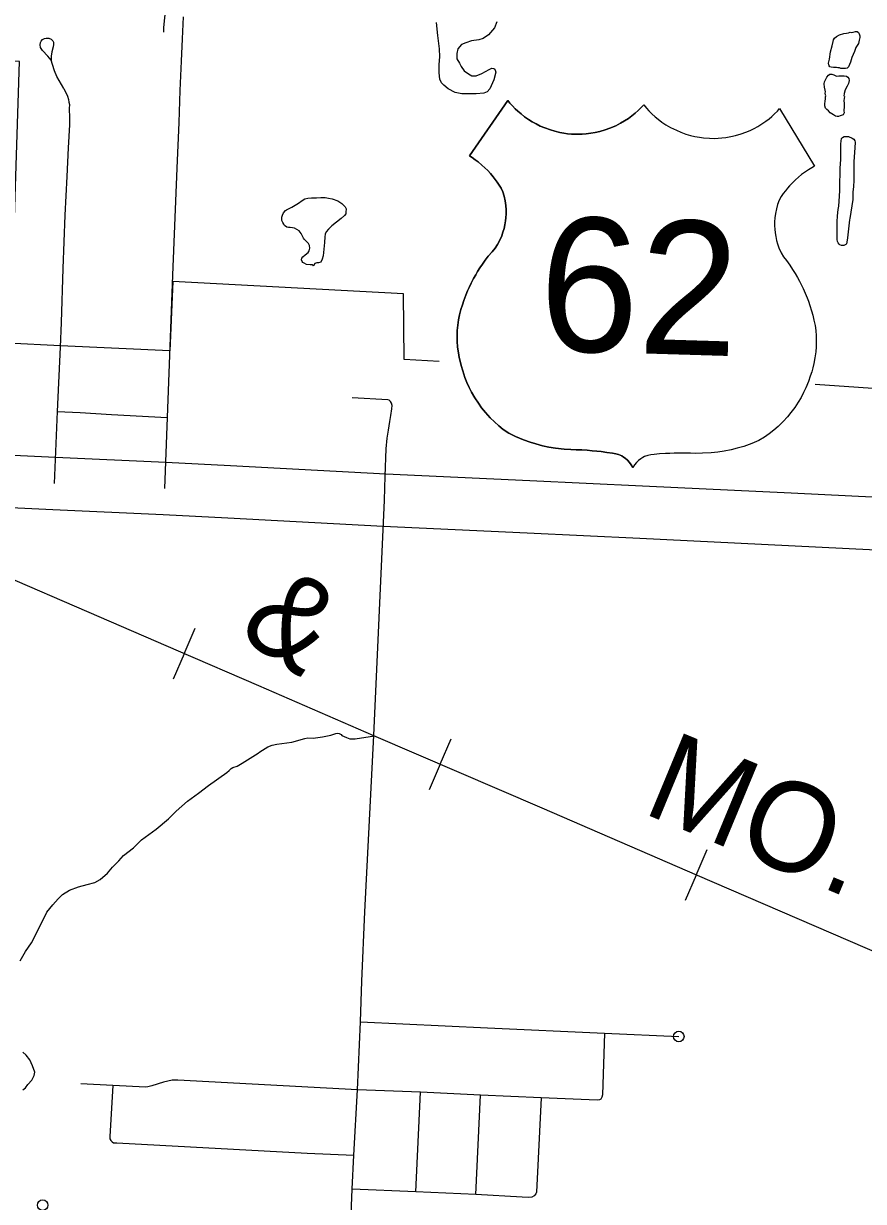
# Model space of a CAD drawing. Extents: x 653372 to 905732, y 627442 to 787275.
# Drawn here: x 676978 to 680953, y 739676 to 745249 of the extents above; entities that cross this region are included whole.
import ezdxf

# ---------------------------------------------------------------- set-up
doc = ezdxf.new("R2010")
doc.units = 0
for name, color, linetype in [('15', 7, 'Continuous'), ('22', 7, 'Continuous'), ('33', 7, 'Continuous'), ('34', 7, 'Continuous'), ('35', 7, 'Continuous'), ('40', 7, 'Continuous'), ('49', 7, 'Continuous'), ('6', 7, 'Continuous')]:
    doc.layers.add(name, color=color, linetype=linetype)

msp = doc.modelspace()

# ---------------------------------------------------------------- linework, layer by layer
at = {"layer": '15'}
for points in [[(674055.1, 743338.2), (674933.5, 743298.8), (675764.1, 743263.3), (676102.5, 743246.2), (677128.2, 743197.8), (677651.3, 743173.3), (677957.3, 743157.7), (678692, 743119.1), (679373.4, 743086.6), (679906.4, 743062.3), (680610.7, 743028), (681281, 742994.8), (682239.3, 742949), (682595.1, 742932.4), (682621, 742930.7), (682881.5, 742919.2), (683054.5, 742911.5), (683924.1, 742873.5), (684678.2, 742833.8)], [(684666.1, 742584.1), (683912, 742623.8), (683043.4, 742661.8), (682870.4, 742669.5), (682607.5, 742681.1), (682581.3, 742682.7), (682227.5, 742699.3), (681268.8, 742745.1), (680598.5, 742778.3), (679894.7, 742812.6), (679361.7, 742836.9), (678679.5, 742869.4), (677944.3, 742908), (677639.1, 742923.6), (677116.5, 742948.1), (676090.3, 742996.5), (675752.4, 743013.6), (674922.5, 743049), (674043.4, 743088.5)]]:
    msp.add_lwpolyline(points, dxfattribs=at)
at = {"layer": '22'}
for points in [[(679913.1, 744864), (679899.5, 744849.6), (679886.5, 744837.1), (679871.8, 744824.1), (679856, 744811.4), (679840.8, 744800.3), (679822.3, 744788.2), (679802.6, 744776.7), (679780.2, 744765.3), (679751.8, 744753.1), (679730.1, 744745.4), (679705.5, 744738.3), (679683.2, 744733.1), (679662.6, 744729.5), (679640.9, 744726.9), (679620.9, 744725.4), (679593.7, 744725), (679571.6, 744725.9), (679552.4, 744727.6), (679534.1, 744730.1), (679515.7, 744733.5), (679492.5, 744738.9), (679471.1, 744745.2), (679445, 744754.6), (679423, 744764), (679403.1, 744773.9), (679384.8, 744784.2), (679368, 744794.7), (679349.2, 744807.9), (679332.1, 744821.3), (679317.3, 744834.1), (679304.9, 744845.8), (679292.3, 744858.8), (679279.9, 744872.6), (679269.9, 744884.7), (679088.9, 744622.4), (679101, 744614.6), (679115.5, 744604.6), (679129.1, 744594.3), (679147.2, 744579.2), (679161.7, 744566), (679174.5, 744553.3), (679187.5, 744539.3), (679200.8, 744523.6), (679210.3, 744511.5), (679219.6, 744498.6), (679229, 744484.6), (679238.2, 744469.8), (679246.5, 744452.6), (679252.6, 744431.5), (679257.1, 744410.7), (679260.2, 744388.5), (679261.7, 744367.9), (679261.8, 744348.1), (679260.7, 744329.6), (679259.1, 744314.7), (679256.1, 744296.6), (679252.2, 744279.5), (679246.8, 744261.1), (679241.1, 744245), (679233.4, 744227), (679221.5, 744203.7), (679209.4, 744185.5), (679195, 744169.3), (679177.4, 744148), (679163.1, 744129.4), (679149.7, 744110.7), (679137.3, 744092.3), (679127, 744075.9), (679117.8, 744060.4), (679107.5, 744042), (679096.4, 744020.5), (679086.3, 743999.5), (679079.4, 743983.8), (679071.1, 743963.7), (679061.9, 743939), (679054.6, 743918.5), (679047.7, 743896), (679041.1, 743869.9), (679036.5, 743846.7), (679033, 743822.4), (679030.6, 743795.8), (679029.7, 743770.8), (679030.1, 743746.3), (679032.2, 743717.5), (679035.9, 743690.2), (679039.7, 743669.5), (679043.9, 743651.3), (679049.2, 743630.7), (679056.4, 743605), (679066.9, 743573.9), (679076.1, 743550.9), (679086.8, 743527.2), (679098.6, 743504), (679114.1, 743477.2), (679130.2, 743452.5), (679145.9, 743431), (679163.8, 743409), (679186.9, 743383.4), (679206.7, 743364), (679227, 743345.9)], [(679913.1, 744864), (679925.8, 744848.8), (679937.9, 744835.6), (679951.8, 744821.7), (679966.9, 744808.1), (679981.4, 744796.1), (679999.1, 744782.9), (680018.1, 744770.2), (680039.8, 744757.5), (680067.4, 744743.6), (680088.6, 744734.6), (680112.7, 744726), (680134.7, 744719.6), (680155, 744714.7), (680176.5, 744710.8), (680196.3, 744708.1), (680223.5, 744706), (680245.6, 744705.6), (680264.9, 744706.2), (680283.3, 744707.6), (680301.9, 744709.9), (680325.4, 744713.9), (680347.1, 744718.9), (680373.7, 744726.7), (680396.2, 744734.8), (680416.7, 744743.5), (680435.6, 744752.6), (680453, 744762.2), (680472.5, 744774.2), (680490.4, 744786.5), (680505.9, 744798.4), (680519, 744809.3), (680532.4, 744821.5), (680545.6, 744834.6), (680556.3, 744846.1), (680721.2, 744573.4), (680708.7, 744566.4), (680693.6, 744557.2), (680679.4, 744547.7), (680660.4, 744533.8), (680645.2, 744521.4), (680631.6, 744509.5), (680617.9, 744496.3), (680603.6, 744481.5), (680593.4, 744469.9), (680583.4, 744457.7), (680573.1, 744444.2), (680563.1, 744430), (680553.7, 744413.3), (680546.4, 744392.7), (680540.7, 744372.1), (680536.2, 744350.1), (680533.5, 744329.7), (680532.2, 744309.9), (680532.1, 744291.4), (680532.9, 744276.5), (680534.8, 744258.2), (680537.7, 744240.9), (680541.9, 744222.2), (680546.7, 744205.8), (680553.2, 744187.3), (680563.8, 744163.4), (680574.8, 744144.5), (680588.2, 744127.4), (680604.4, 744105.2), (680617.6, 744085.7), (680629.9, 744066.2), (680641.1, 744047.2), (680650.5, 744030.1), (680658.7, 744014.2), (680667.9, 743995.1), (680677.7, 743973), (680686.4, 743951.4), (680692.4, 743935.3), (680699.5, 743914.8), (680707.2, 743889.6), (680713.2, 743868.7), (680718.8, 743845.8), (680723.8, 743819.4), (680727, 743795.9), (680729, 743771.4), (680729.8, 743744.8), (680729.2, 743719.8), (680727.3, 743695.4), (680723.5, 743666.7), (680718.2, 743639.7), (680713.1, 743619.2), (680707.9, 743601.3), (680701.4, 743581.1), (680692.7, 743555.9), (680680.3, 743525.4), (680669.8, 743503), (680657.7, 743480.1), (680644.4, 743457.6), (680627.4, 743431.8), (680609.8, 743408.1), (680592.9, 743387.6), (680573.7, 743366.6), (680549, 743342.5), (680528.2, 743324.3), (680506.8, 743307.5)], [(679227, 743345.9), (679248.2, 743328.8), (679273.8, 743311), (679306.1, 743295.4), (679343.9, 743279.5), (679374.9, 743268.4), (679402.8, 743259.8), (679434.4, 743251.5), (679464.1, 743245.1), (679496.1, 743239.7), (679536.4, 743235), (679567.3, 743233), (679593.8, 743232.4), (679619.6, 743231.3), (679645.3, 743229.7), (679669.7, 743227.8), (679691, 743225.7), (679711.9, 743223.3), (679738.7, 743219.7), (679764.9, 743215.7), (679780.6, 743213), (679793.6, 743210), (679809.1, 743203), (679818, 743197.8), (679825.7, 743192.3), (679836.2, 743183.3), (679846.2, 743172.5), (679854.3, 743161.5), (679861.6, 743148.8)], [(680506.8, 743307.5), (680484.6, 743291.7), (680458, 743275.5), (680424.8, 743261.8), (680386.1, 743248.2), (680354.5, 743239), (680326.1, 743232.1), (680294.1, 743225.7), (680264.1, 743221.1), (680231.8, 743217.6), (680191.3, 743215.4), (680160.3, 743215.2), (680133.8, 743216.1), (680108, 743216.6), (680082.3, 743216.6), (680057.8, 743216.1), (680036.4, 743215.3), (680015.4, 743214.2), (679988.4, 743212.2), (679962, 743209.7), (679946.2, 743208), (679933.1, 743205.8), (679917.2, 743199.8), (679908, 743195.1), (679900, 743190.1), (679888.9, 743181.7), (679878.3, 743171.6), (679869.6, 743161), (679861.6, 743148.8)]]:
    msp.add_lwpolyline(points, dxfattribs=at)
at = {"layer": '33'}
for points in [[(677733.3, 745281.3), (677727.7, 745177), (677723.2, 745070.8), (677717.8, 744931.3), (677712.6, 744781.2), (677703, 744564), (677683.3, 744057.5), (677657.9, 743384.7), (677645.2, 743048.5)], [(677168.2, 744941.7), (677185.3, 744904.7), (677190, 744890.2), (677192.5, 744877.3), (677194.7, 744865.1), (677193.5, 744846.2), (677194.4, 744802.7), (677194.4, 744769.7), (677188.9, 744661.4), (677182.6, 744524.9), (677173.2, 744341.7), (677164.4, 744090), (677155.7, 743833.6), (677151, 743717.7), (677136.9, 743413), (677122.3, 743073)], [(678685.8, 742994.2), (678688.7, 743107), (678694.6, 743235.9), (678698.7, 743287.8), (678704.4, 743325.4), (678711.7, 743365.9), (678716.2, 743394.4), (678720.7, 743425.3), (678721.6, 743441.1), (678719.9, 743451.9), (678714, 743460.2), (678708.6, 743466.5), (678702.5, 743467.7), (678533.5, 743477.9)], [(677136.9, 743413), (677245.2, 743408.5), (677393.2, 743399.7), (677657.9, 743384.7)], [(678446, 737776.3), (678468.8, 738303.5), (678483.2, 738601.3), (678499.8, 738933.7), (678512.4, 739223.8), (678533.8, 739734.2), (678541.5, 739894.8), (678558.6, 740203.3), (678572.7, 740525.6), (678579.2, 740718.4), (678593.6, 741046), (678635.3, 741880.7), (678685.8, 742994.2)], [(678572.7, 740525.6), (679173.6, 740497.6), (679727.7, 740471.8), (680078.9, 740456.3)], [(679727.7, 740471.8), (679717.2, 740180.2), (679715.2, 740169.4), (679713.4, 740165.3), (679709.5, 740160), (679703.6, 740156.8), (679693.1, 740155.1), (679428.2, 740166.4), (679141.1, 740179.4), (678856.7, 740192.1), (678558.6, 740203.3)], [(678558.6, 740203.3), (677708, 740250), (677681.5, 740249.2), (677660.6, 740245.6), (677640.3, 740240.4), (677585.1, 740222.1), (677566.7, 740218.5), (677556.4, 740216.3), (677400.5, 740224.3), (677249.5, 740233)], [(677400.5, 740224.3), (677385.8, 739983.6), (677386.3, 739972.7), (677390.2, 739964.3), (677396.7, 739957.4), (677404, 739953.9), (677419.8, 739953.4), (678319.8, 739904), (678541.5, 739894.8)], [(678834.3, 739721.4), (678856.7, 740192.1)], [(679428.2, 740166.4), (679405.1, 739720.1), (679402.9, 739711.8), (679394.3, 739702.1), (679383.3, 739696.6), (679366.6, 739693.8), (679337.6, 739696.3), (679117.8, 739707.9), (678834.3, 739721.4), (678533.8, 739734.2)], [(679117.8, 739707.9), (679141.1, 740179.4)]]:
    msp.add_lwpolyline(points, dxfattribs=at)
for centre in [(680078.9, 740456.3), (677068.1, 739658.6)]:
    msp.add_circle(centre, 25, dxfattribs=at)
at = {"layer": '34'}
for points in [[(677108.1, 745075), (677092.5, 745094.1), (677066.9, 745121.9), (677058.5, 745134.8), (677055.9, 745147.7), (677057.2, 745158.4), (677060.9, 745166.1), (677067, 745172.6), (677076.4, 745177.7), (677085.3, 745180.1), (677097.5, 745180.2), (677108.7, 745174.2), (677115.9, 745167.1), (677119, 745160), (677119.1, 745149.2), (677117.4, 745138.5), (677111.8, 745115.1), (677107.7, 745094.2), (677108.1, 745075)], [(677168.2, 744941.7), (677134.7, 744998.8), (677124.7, 745025), (677114.9, 745055.7), (677108.1, 745075)]]:
    msp.add_lwpolyline(points, dxfattribs=at)
at = {"layer": '35'}
for points in [[(677644.7, 745359.2), (677649.1, 745321.6), (677640.8, 745230.8), (677640.1, 745208)], [(678938.4, 745192.1), (678932.2, 745254.3)], [(679207, 745227.8), (679177.6, 745196.1), (679152.7, 745178.5), (679133.1, 745171), (679097.4, 745167), (679071.7, 745157.6), (679051.1, 745149), (679033.2, 745129.2), (679028.4, 745107), (679028.7, 745081.5), (679040.3, 745061.8), (679049, 745046.3), (679063.6, 745025.5), (679083.5, 745010.7), (679099.5, 745001), (679119.9, 745001.4), (679146.6, 745011.8), (679181.8, 745031.1), (679194.2, 745036.9), (679203.3, 745036.6), (679208.3, 745032.4), (679212.9, 745018), (679203.7, 744982.6), (679185.1, 744939.4), (679172.5, 744925.6), (679156, 744919), (679119.3, 744916), (679083.7, 744916), (679052.2, 744916), (679019.8, 744922), (678987.8, 744940.3), (678967, 744957.2), (678955.1, 744968.7), (678947.5, 744985.3), (678945.4, 745015.8), (678944.5, 745055.5), (678948.6, 745091), (678946.7, 745128.7), (678938.4, 745192.1)], [(679218.1, 745256.9), (679207, 745227.8)], [(680797, 745114.2), (680804.7, 745142.9), (680808.8, 745164), (680811.7, 745171.9), (680816.1, 745179.4), (680824.7, 745186.7), (680838.9, 745194.7), (680860.8, 745201.2), (680872.6, 745202.8), (680882.1, 745204.4), (680890.2, 745207.2), (680894.8, 745207), (680904.3, 745208.3), (680915.4, 745211), (680923, 745211.1), (680928.9, 745207.1), (680932.9, 745199.8), (680936.4, 745190.2), (680936.2, 745182.6), (680932.8, 745169.8), (680928.9, 745153.6), (680917.3, 745135.3), (680909.9, 745117.3)], [(680909.9, 745117.3), (680897.3, 745088.4), (680890.9, 745066.6), (680882.6, 745043.3), (680875.6, 745037.4), (680868, 745036.1), (680857.3, 745035.7), (680845.9, 745035.7), (680839.2, 745039.7), (680832.4, 745039.9), (680824.8, 745040.1), (680811.2, 745041.3), (680800.6, 745042.7), (680794.2, 745044.4), (680790.9, 745048.3), (680789.1, 745053.3), (680788.2, 745061.3), (680791.8, 745079.8), (680797, 745114.2)], [(680774.1, 744906.3), (680772.7, 744911.7), (680771.5, 744919.7), (680773.5, 744925.7), (680772.3, 744934.1), (680768.1, 744948.3), (680766.7, 744963.1), (680768.1, 744972.6), (680773.3, 744982.7), (680779.4, 744994.7), (680787.6, 745003.9), (680793.1, 745008.7), (680802.6, 745009.2), (680813.2, 745006.6), (680825.5, 745000.1), (680836.9, 745000.9), (680862.4, 745001.3), (680873, 744999.4), (680879.7, 744995.1), (680883.3, 744989.3), (680885.2, 744978.9), (680882.6, 744965.7), (680875.7, 744953), (680866.5, 744935.4), (680862.2, 744918.5), (680859.9, 744904.5), (680859.9, 744904.5)], [(680862.5, 744902.9), (680860.4, 744884), (680862.2, 744870.2), (680862.2, 744856.2), (680860.8, 744836.5), (680861.3, 744827), (680860.4, 744823.2), (680856.5, 744817.6), (680842.3, 744811.6), (680835, 744809.1), (680829.2, 744808.6), (680821.3, 744809.9), (680810.5, 744816.3), (680796, 744827), (680786.8, 744835.3), (680779.4, 744841.6), (680773.9, 744848.2), (680769.6, 744859.3), (680769.9, 744869.6), (680771.8, 744882.1), (680772.5, 744892.7), (680774, 744902.1), (680774.1, 744906.3)], [(680838.3, 744407.8), (680840.9, 744457.3), (680841.5, 744489.5), (680841.2, 744505.1), (680842.3, 744530.2), (680843, 744564), (680845.7, 744605.6), (680846.4, 744679.2), (680848.4, 744705.4), (680853.4, 744710.2), (680862.3, 744713.7), (680870.3, 744715), (680881.7, 744713.9), (680899.3, 744705.8), (680907.1, 744701.3), (680911.8, 744694), (680913.9, 744687.8), (680911.6, 744660.9), (680908.1, 744595.7), (680907.7, 744544.4), (680908.1, 744506.1), (680906.5, 744478.4), (680903.4, 744450.7), (680902.2, 744416.8)], [(678307.1, 744226.9), (678303, 744233.1), (678298.6, 744243.1), (678291.5, 744256), (678282.5, 744268), (678271, 744274.4), (678260.8, 744279.9), (678251, 744282.1), (678240.3, 744283.3), (678232.3, 744284.5), (678223.4, 744285.7), (678213.3, 744292.6), (678209.3, 744299.8), (678204.9, 744307.9), (678199.5, 744316.9), (678200, 744332), (678202.6, 744342.7), (678208.6, 744353.8), (678217.4, 744364.3), (678222.1, 744367), (678231.2, 744372.3), (678247.4, 744380.3), (678279.4, 744399.5), (678297.1, 744411.6), (678309.5, 744418.8), (678322.8, 744422.1), (678340.2, 744424.4), (678364.1, 744424.6), (678385.3, 744425), (678404.5, 744425.3), (678421.3, 744422.5)], [(678421.3, 744422.5), (678437.7, 744419.6), (678465.1, 744409.9), (678483.4, 744397.1), (678499.4, 744381.6), (678504.8, 744372.6), (678503.8, 744357.1), (678503.5, 744348.2), (678497.2, 744340.4), (678480.4, 744325.9), (678436.2, 744291.5), (678420.7, 744275.6), (678410, 744262.8), (678404.5, 744252.6), (678403.2, 744240), (678401.4, 744213.3), (678398.6, 744181), (678395.3, 744150.1), (678391.5, 744133.8), (678384.1, 744119.9), (678374.1, 744116.4), (678365.2, 744116.2), (678356.2, 744114.2), (678350.9, 744107.8), (678350.8, 744104), (678348.4, 744101.7), (678346.6, 744104.6), (678344.8, 744107), (678340.1, 744107.1), (678334.4, 744106.4), (678316.7, 744109.3), (678306, 744114.3), (678300.1, 744118.2), (678296.5, 744123.5), (678292.9, 744130.6), (678294.1, 744138.1), (678299.4, 744145), (678311, 744154.5), (678324, 744165.4), (678329.9, 744174.1), (678332.6, 744186.2), (678331.6, 744198.5), (678326.2, 744208), (678313.9, 744221), (678307.1, 744226.9)], [(680902.2, 744416.8), (680893.7, 744356), (680888.6, 744326.9), (680886.1, 744319.4), (680877.2, 744234.9), (680874.6, 744213.7), (680872.9, 744206.2), (680869.4, 744202.9), (680859.4, 744199), (680851.8, 744198.5), (680848.3, 744198.6), (680841.6, 744201.8), (680838.3, 744205.3), (680833.1, 744211.2), (680830.3, 744217), (680828.3, 744227.3), (680827.9, 744250.5), (680828.6, 744288.4), (680827.8, 744312.8), (680829.4, 744337.8), (680831.4, 744354.4), (680832.9, 744368.5), (680835.7, 744385.1), (680838.3, 744407.8)], [(676961.4, 740814.3), (676987.5, 740858.7), (677014.7, 740899.6), (677053, 740972.9), (677087.9, 741044.1), (677116, 741079.4), (677141.6, 741106.8), (677161.4, 741127.6), (677194.8, 741148.1), (677237, 741163.7), (677279, 741174.9), (677314.3, 741185.1), (677340.7, 741198.9), (677375.4, 741229.5), (677398.8, 741257), (677427.9, 741287.7), (677450.1, 741313), (677498.3, 741349.5), (677536.6, 741386.7), (677604.6, 741436.6), (677663.7, 741486.7), (677700.8, 741521.7), (677753, 741569.8), (677806.1, 741607.7), (677853.4, 741643.5), (677940.3, 741704.7), (677950.7, 741714.3), (677960, 741724.2), (677968.6, 741728.4), (677988.5, 741734.6), (678012.7, 741750), (678088, 741797.1), (678096.6, 741802.4), (678134.5, 741826.4), (678155.1, 741835.1), (678176.7, 741839.8), (678248, 741849), (678308.3, 741866.1), (678322.5, 741869), (678348.4, 741867.1), (678393.2, 741873.9), (678432.6, 741881.5), (678455.4, 741890.4), (678464.2, 741891.3), (678470.9, 741890.3), (678480.9, 741884.4), (678484.4, 741879.9), (678505.6, 741871.4), (678521.8, 741864.7), (678547.1, 741864.5), (678638.4, 741878.7)], [(676974.7, 740204.3), (676986.2, 740214.1), (676997.9, 740228.4), (677016.7, 740250.4), (677027.4, 740271.5), (677031.3, 740287.2), (677019.8, 740318), (677008.2, 740345.4), (676990.8, 740367.4), (676974.3, 740381.4)]]:
    msp.add_lwpolyline(points, dxfattribs=at)
at = {"layer": '40'}
for p, q in [((677737.5, 742267.4), (677789.7, 742388.6)), ((677737.5, 742267.4), (677685.2, 742146.2)), ((678949.3, 741744.1), (679001.6, 741865.3)), ((678949.3, 741744.1), (678897, 741623)), ((680160.9, 741220.2), (680213.3, 741341.3)), ((680160.9, 741220.2), (680108.4, 741099.1))]:
    msp.add_line(p, q, dxfattribs=at)
msp.add_lwpolyline([(681040.8, 740840.9), (680166.9, 741217.6), (679431.5, 741536), (678636, 741879.4), (678091.2, 742115), (677710.3, 742279.1), (677336.3, 742441), (676830.4, 742658.9)], dxfattribs=at)
msp.add_lwpolyline([(681040.8, 740840.9), (680166.9, 741217.6), (679431.5, 741536), (678636, 741879.4), (678091.2, 742115), (677710.3, 742279.1), (677336.3, 742441), (676830.4, 742658.9)], dxfattribs=at)
at = {"layer": '49'}
for points in [[(679227, 743345.9), (679206.7, 743364), (679186.9, 743383.4), (679163.8, 743409), (679145.9, 743431), (679130.2, 743452.5), (679114.1, 743477.2), (679098.6, 743504), (679086.8, 743527.2), (679076.1, 743550.9), (679066.9, 743573.9), (679056.4, 743605), (679049.2, 743630.7), (679043.9, 743651.3), (679039.7, 743669.5), (679035.9, 743690.2), (679032.2, 743717.5), (679030.1, 743746.3), (679029.7, 743770.8), (679030.6, 743795.8), (679033, 743822.4), (679036.5, 743846.7), (679041.1, 743869.9), (679047.7, 743896), (679054.6, 743918.5), (679061.9, 743939), (679071.1, 743963.7), (679079.4, 743983.8), (679086.3, 743999.5), (679096.4, 744020.5), (679107.5, 744042), (679117.8, 744060.4), (679127, 744075.9), (679137.3, 744092.3), (679149.7, 744110.7), (679163.1, 744129.4), (679177.4, 744148), (679195, 744169.3), (679209.4, 744185.5), (679221.5, 744203.7), (679233.4, 744227), (679241.1, 744245), (679246.8, 744261.1), (679252.2, 744279.5), (679256.1, 744296.6), (679259.1, 744314.7), (679260.7, 744329.6), (679261.8, 744348.1), (679261.7, 744367.9), (679260.2, 744388.5), (679257.1, 744410.7), (679252.6, 744431.5), (679246.5, 744452.6), (679238.2, 744469.8), (679229, 744484.6), (679219.6, 744498.6), (679210.3, 744511.5), (679200.8, 744523.6), (679187.5, 744539.3), (679174.5, 744553.3), (679161.7, 744566), (679147.2, 744579.2), (679129.1, 744594.3), (679115.5, 744604.6), (679101, 744614.6), (679088.9, 744622.4), (679269.9, 744884.7), (679279.9, 744872.6), (679292.3, 744858.8), (679304.9, 744845.8), (679317.3, 744834.1), (679332.1, 744821.3), (679349.2, 744807.9), (679368, 744794.7), (679384.8, 744784.2), (679403.1, 744773.9), (679423, 744764), (679445, 744754.6), (679471.1, 744745.2), (679492.5, 744738.9), (679515.7, 744733.5), (679534.1, 744730.1), (679552.4, 744727.6), (679571.6, 744725.9), (679593.7, 744725), (679620.9, 744725.4), (679640.9, 744726.9), (679662.6, 744729.5), (679683.2, 744733.1), (679705.5, 744738.3), (679730.1, 744745.4), (679751.8, 744753.1), (679780.2, 744765.3), (679802.6, 744776.7), (679822.3, 744788.2), (679840.8, 744800.3), (679856, 744811.4), (679871.8, 744824.1), (679886.5, 744837.1), (679899.5, 744849.6), (679913.1, 744864)], [(679913.1, 744864), (679925.8, 744848.8), (679937.9, 744835.6), (679951.8, 744821.7), (679966.9, 744808.1), (679981.4, 744796.1), (679999.1, 744782.9), (680018.1, 744770.2), (680039.8, 744757.5), (680067.4, 744743.6), (680088.6, 744734.6), (680112.7, 744726), (680134.7, 744719.6), (680155, 744714.7), (680176.5, 744710.8), (680196.3, 744708.1), (680223.5, 744706), (680245.6, 744705.6), (680264.9, 744706.2), (680283.3, 744707.6), (680301.9, 744709.9), (680325.4, 744713.9), (680347.1, 744718.9), (680373.7, 744726.7), (680396.2, 744734.8), (680416.7, 744743.5), (680435.6, 744752.6), (680453, 744762.2), (680472.5, 744774.2), (680490.4, 744786.5), (680505.9, 744798.4), (680519, 744809.3), (680532.4, 744821.5), (680545.6, 744834.6), (680556.3, 744846.1), (680721.2, 744573.4), (680708.7, 744566.4), (680693.6, 744557.2), (680679.4, 744547.7), (680660.4, 744533.8), (680645.2, 744521.4), (680631.6, 744509.5), (680617.9, 744496.3), (680603.6, 744481.5), (680593.4, 744469.9), (680583.4, 744457.7), (680573.1, 744444.2), (680563.1, 744430), (680553.7, 744413.3), (680546.4, 744392.7), (680540.7, 744372.1), (680536.2, 744350.1), (680533.5, 744329.7), (680532.2, 744309.9), (680532.1, 744291.4), (680532.9, 744276.5), (680534.8, 744258.2), (680537.7, 744240.9), (680541.9, 744222.2), (680546.7, 744205.8), (680553.2, 744187.3), (680563.8, 744163.4), (680574.8, 744144.5), (680588.2, 744127.4), (680604.4, 744105.2), (680617.6, 744085.7), (680629.9, 744066.2), (680641.1, 744047.2), (680650.5, 744030.1), (680658.7, 744014.2), (680667.9, 743995.1), (680677.7, 743973), (680686.4, 743951.4), (680692.4, 743935.3), (680699.5, 743914.8), (680707.2, 743889.6), (680713.2, 743868.7), (680718.8, 743845.8), (680723.8, 743819.4), (680727, 743795.9), (680729, 743771.4), (680729.8, 743744.8), (680729.2, 743719.8), (680727.3, 743695.4), (680723.5, 743666.7), (680718.2, 743639.7), (680713.1, 743619.2), (680707.9, 743601.3), (680701.4, 743581.1), (680692.7, 743555.9), (680680.3, 743525.4), (680669.8, 743503), (680657.7, 743480.1), (680644.4, 743457.6), (680627.4, 743431.8), (680609.8, 743408.1), (680592.9, 743387.6), (680573.7, 743366.6), (680549, 743342.5), (680528.2, 743324.3), (680506.8, 743307.5)], [(679861.6, 743148.8), (679854.3, 743161.5), (679846.2, 743172.5), (679836.2, 743183.3), (679825.7, 743192.3), (679818, 743197.8), (679809.1, 743203), (679793.6, 743210), (679780.6, 743213), (679764.9, 743215.7), (679738.7, 743219.7), (679711.9, 743223.3), (679691, 743225.7), (679669.7, 743227.8), (679645.3, 743229.7), (679619.6, 743231.3), (679593.8, 743232.4), (679567.3, 743233), (679536.4, 743235), (679496.1, 743239.7), (679464.1, 743245.1), (679434.4, 743251.5), (679402.8, 743259.8), (679374.9, 743268.4), (679343.9, 743279.5), (679306.1, 743295.4), (679273.8, 743311), (679248.2, 743328.8), (679227, 743345.9)], [(680506.8, 743307.5), (680484.6, 743291.7), (680458, 743275.5), (680424.8, 743261.8), (680386.1, 743248.2), (680354.5, 743239), (680326.1, 743232.1), (680294.1, 743225.7), (680264.1, 743221.1), (680231.8, 743217.6), (680191.3, 743215.4), (680160.3, 743215.2), (680133.8, 743216.1), (680108, 743216.6), (680082.3, 743216.6), (680057.8, 743216.1), (680036.4, 743215.3), (680015.4, 743214.2), (679988.4, 743212.2), (679962, 743209.7), (679946.2, 743208), (679933.1, 743205.8), (679917.2, 743199.8), (679908, 743195.1), (679900, 743190.1), (679888.9, 743181.7), (679878.3, 743171.6), (679869.6, 743161), (679861.6, 743148.8)]]:
    msp.add_lwpolyline(points, dxfattribs=at)
at = {"layer": '6'}
for points in [[(678944.6, 743650.2), (678779.8, 743659.2), (678775.6, 743970.4), (677684.2, 744028.4), (677669.6, 743699.7), (677152.3, 743723.9), (676901.5, 743736.5), (676933, 744280.7), (676958.8, 745069.2), (676062, 745105.1)], [(682091.5, 743467.9), (681294.3, 743501.3), (680723.6, 743541)]]:
    msp.add_lwpolyline(points, dxfattribs=at)

# ---------------------------------------------------------------- texts
at = {"layer": '22'}
msp.add_text('62', height=633.6, rotation=358.28, dxfattribs=at).set_placement((679411.1, 743703))
at = {"layer": '40'}
for s, rotation, p in [('&', 326.2663, (677982.2, 742359.9)), ('MO.', 337.4797, (679898.5, 741517.3))]:
    msp.add_text(s, height=422.4, rotation=rotation, dxfattribs=at).set_placement(p)

doc.saveas('drawing.dxf')
